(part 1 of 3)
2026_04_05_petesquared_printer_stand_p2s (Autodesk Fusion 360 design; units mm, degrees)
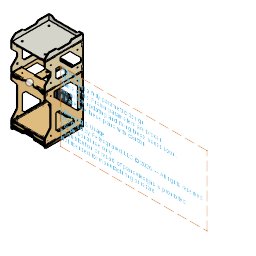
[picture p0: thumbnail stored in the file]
parameter "material_thickness" = 12.192
parameter "printer_width_padding" = 482.6 (= "ceil(printer_width_adjusted + 1 in)")
parameter "printer_length_padding" = 609.6 (= "ceil(printer_length_adjusted + 4 in)")
parameter "printer_height_padding" = 736.6 (= "ceil(printer_height_adjusted + global_shelf_height + printer_height_pad)")
parameter "global_shelf_height" = 71.12
parameter "shelf_padding_sides" = 28.702 (= "material_thickness + 0.65 in")
parameter "ams_height" = 223.012
parameter "global_shelf_width" = 428.498 (= "printer_width_adjusted - shelf_padding_sides")
parameter "global_shelf_length" = 457.2
parameter "filament_height" = 228.6
parameter "base_height" = 38.1
parameter "poop_height" = 101.6
parameter "hole_bolt" = 10.414 comment "The furniture bolts for bolting stand and shelves togther"
parameter "dado_bolthead_diameter" = 16.256 comment "Head size of furniture bolts for bolting stand and shelves togther"
parameter "dado_bolthead_depth" = 3.048 comment "The inset dado to fit the furniture bolt heads flush with plywood surface"
parameter "bolt_side_offset" = 76.2
parameter "handle_inset_depth" = 19.05
parameter "handle_angle_side" = 15
parameter "handle_width" = 152.4
parameter "global_cutout_padding" = 44.45
parameter "global_cutout_corner_round" = 12.7
parameter "shelf_runner_inset" = 15.748 comment "If you are using different drawer runners this will need to be adjusted."
parameter "dado_material_thickness" = 12.446 (= "material_thickness + 0.01 in")
parameter "dado_material_depth" = 4.572
parameter "hole_screw" = 3.2004
parameter "hole_screwhead" = 7.112
parameter "dado_screwhead_depth" = 3.302
parameter "switch_diameter" = 25.4
parameter "printer_width" = 388.9375 (= "15 5/16")
parameter "printer_width_adjusted" = 457.2 (= "ceil(( min(60 in; max(12 in; printer_width)) ) + printer_width_pad)")
parameter "printer_width_pad" = 50.8
parameter "printer_length" = 388.9375 (= "15 5/16")
parameter "printer_length_adjusted" = 508 (= "ceil(( min(60 in; max(12 in; printer_length)) ) + printer_length_pad)")
parameter "printer_length_pad" = 101.6
parameter "printer_height" = 466.725 (= "18 3/8")
parameter "printer_height_pad" = 50.8
parameter "hole_screw_inset" = 38.1
parameter "hole_screws_width_distance" = 381 (= "( printer_width_adjusted - ( hole_screw_inset * 2 ) )")
parameter "hole_screws_length_distance" = 431.8 (= "( printer_length_adjusted - ( hole_screw_inset * 2 ) )")
parameter "hole_screws_printer_height_distance" = 533.4 (= "( printer_height_adjusted - ( hole_screw_inset * 2 ) )")
parameter "hole_switch_button" = 19.431
parameter "milling_pins_twosided" = 9.525
parameter "storage_height" = 25.4
parameter "slot_screw_width" = 38.1
parameter "dado_screwhead_carpentry" = 10.16
parameter "hole_screws_ams_height_distance" = 279.4 (= "( ams_height_adjusted - ( hole_screw_inset * 2 ) )")
parameter "ams_height_pad" = 50.8 comment "adjusts the padding space above the ams"
parameter "filament_height_pad" = 0 comment "adjusts the padding space above the filament"
parameter "hole_screws_filament_height_distance" = 228.6 (= "( filament_height_adjusted - ( hole_screw_inset * 2 ) )")
parameter "storage_height_pad" = 76.2
parameter "hole_screws_storage_height_distance" = 101.6 (= "( storage_height_adjusted - ( hole_screw_inset * 2 ) )")
parameter "poop_height_pad" = 25.4
parameter "hole_screws_poop_height_distance" = 177.8 (= "( poop_height_adjusted - ( hole_screw_inset * 2 ) )")
parameter "brace_length" = 139.7
parameter "hole_screw_brace_offset" = 25.4
parameter "wall_thickness_3d_printed" = 4.572
parameter "runner_thickness" = 13.1572
parameter "hole_screw_3dprint" = 3.81
parameter "hole_threaded_inserts" = 12.192
parameter "d545" = 25.4
parameter "d546" = 25.4 (= "d545")
parameter "d2170" = 12.7
parameter "d2974" = 19.05
sketch "printer_width_length" plane through (0, 0, 0) normal (0, 0, 1) x axis (1, 0, 0)
  line L1 (194.4688, 388.9375) -> (-194.4688, 388.9375)
  line L2 (194.4688, 0) -> (194.4688, 388.9375)
  line L3 (-194.4688, 0) -> (194.4688, 0)
  line L4 (-194.4688, 388.9375) -> (-194.4688, 0)
  line L5 (0, 0) -> (0, 388.9375)
  line L6 (194.4688, 194.4688) -> (-194.4688, 194.4688)
  point P6 (0, 0)
  point P1 (0, 0)
  point P7 (0, 388.9375)
  point P8 (0, 0)
  point P9 (-194.4688, 194.4688)
  point P10 (194.4688, 194.4688)
  point P11 (0, 194.4688)
  point P3 (194.4688, 388.9375)
  point P4 (194.4688, 0)
  point P5 (-194.4688, 0)
  horizontal L1
  vertical L2
  horizontal L3
  vertical L4
  midpoint L3 P6
  coincident P1 P6
  midpoint L1 P7
  coincident P6 P8
  midpoint L4 P9
  midpoint L2 P10
  midpoint L5 P11
  dimension "d2" distance P3 P4 = 388.9375 (= "printer_length")
  dimension "d24" distance P4 P5 = 388.9375 (= "printer_width")
work_plane "WorkPlane7" AlongDistance 0
work_plane "WorkPlane6" AlongDistance 466.725 (= "printer_height")
work_plane "WorkPlane3" RotateAngle 90
work_plane "WorkPlane4" RotateAngle 90
work_plane "WorkPlane5" RotateAngle 90
sketch "printer_length_height" plane through (194.4687, 0, 0) normal (-1, 0, 0) x axis (0, -1, 0)
  line L1 (0, 0) -> (-388.9375, 0)
  line L2 (0, 466.725) -> (0, 0)
  line L3 (-388.9375, 466.725) -> (0, 466.725)
  line L4 (-388.9375, 0) -> (-388.9375, 466.725)
  line L5 (-194.4687, 466.725) -> (-194.4688, 0)
  line L6 (-388.9375, 233.3625) -> (0, 233.3625)
  point P3 (0, 0)
  point P4 (0, 0)
  point P2 (-388.9375, 0)
  point P7 (-388.9375, 0)
  point P8 (-194.4688, 0)
  point P9 (-194.4687, 466.725)
  point P10 (0, 233.3625)
  point P11 (-388.9375, 233.3625)
  point P12 (-194.4687, 233.3625)
  point P5 (0, 466.725)
  coincident P3 P4
  perpendicular L1 L2
  perpendicular L2 L3
  coincident P2 P7
  perpendicular L1 L4
  midpoint L1 P8
  midpoint L3 P9
  midpoint L2 P10
  midpoint L4 P11
  midpoint L5 P12
  dimension "d23" distance P4 P5 = 466.725 (= "printer_height")
sketch "printer_height_length" plane through (0, 388.9375, 0) normal (0, -1, 0) x axis (-1, 0, 0)
  line L1 (-194.4688, 0) -> (-194.4688, -466.725)
  line L2 (-194.4688, 0) -> (194.4688, 0)
  line L3 (194.4688, -466.725) -> (-194.4688, -466.725)
  line L4 (194.4688, 0) -> (194.4688, -466.725)
  line L5 (0, 0) -> (0, -466.725)
  line L6 (194.4688, -233.3625) -> (-194.4688, -233.3625)
  point P2 (-194.4688, -466.725)
  point P6 (-194.4688, -466.725)
  point P4 (194.4688, 0)
  point P8 (194.4688, 0)
  point P9 (0, -466.725)
  point P1 (0, 0)
  point P10 (0, 0)
  point P11 (-194.4688, -233.3625)
  point P12 (194.4688, -233.3625)
  point P13 (0, -233.3625)
  coincident P2 P6
  perpendicular L1 L3
  coincident P4 P8
  perpendicular L2 L4
  midpoint L3 P9
  coincident P1 P10
  midpoint L1 P11
  midpoint L4 P12
  midpoint L6 P13
extrude "Extrude1" new body sketch "printer_width_length" profile of L1 L2 L3 L4 along normal blind 466.725 (= "printer_height") bodies "printer_size"
fillet "Fillet1" radius 40.64
work_plane "WorkPlane5"
work_plane "WorkPlane1" AlongDistance 538.48 (= "printer_height_adjusted - global_shelf_height")
work_plane "WorkPlane2" AlongDistance 508 (= "printer_length_adjusted")
work_plane "WorkPlane7" RotateAngle 0
work_plane "WorkPlane6" RotateAngle 90
work_plane "WorkPlane8" AlongDistance 228.6 (= "printer_width_adjusted / 2")
work_plane "WorkPlane4" AlongDistance 304.8 (= "printer_height_adjusted / 2")
work_plane "WorkPlane9" AlongDistance 0
sketch "printer_bottom" plane through (0, 0, -71.12) normal (0, 0, 1) x axis (1, 0, 0)
  line L1 (228.6, 508) -> (-228.6, 508)
  line L2 (228.6, 0) -> (228.6, 508)
  line L3 (-228.6, 0) -> (228.6, 0)
  line L4 (-228.6, 508) -> (-228.6, 0)
  line L5 (152.4, 76.2) -> (152.4, 431.8)
  line L6 (-152.4, 76.2) -> (152.4, 76.2)
  line L7 (-152.4, 431.8) -> (-152.4, 76.2)
  line L8 (152.4, 431.8) -> (-152.4, 431.8)
  line L9 (48.9938, 19.05) -> (-48.9938, 19.05)
  line L10 (216.408, 12.192) -> (220.98, 12.192)
  line L11 (0, 0) -> (0, 508)
  line L12 (-216.408, 12.192) -> (-220.98, 12.192)
  line L13 (-220.98, 508) -> (-220.98, 12.192)
  line L14 (220.98, 12.192) -> (220.98, 508)
  line L15 (228.6, 254) -> (-228.6, 254)
  line L16 (0, 254) -> (-228.6, 508)
  line L17 (228.6, 508) -> (0, 254)
  line L18 (-228.6, 0) -> (0, 254)
  line L19 (228.6, 0) -> (0, 254)
  line L20 (-81.28, 500.38) -> (-220.98, 500.38)
  line L21 (-220.98, 500.38) -> (-220.98, 360.68)
  line L22 (-204.216, 360.68) -> (-220.98, 360.68)
  line L23 (-81.28, 483.616) -> (-81.28, 500.38)
  line L24 (220.98, 139.7) -> (-220.98, 139.7)
  line L25 (-103.0086, 418.3296) -> (-81.28, 483.616)
  line L26 (-204.216, 360.68) -> (-138.9296, 382.4086)
  line L27 (216.408, 12.192) -> (165.608, 0)
  line L28 (-76.2, 0) -> (-48.9938, 19.05)
  line L29 (76.2, 0) -> (48.9938, 19.05)
  line L30 (-216.408, 12.192) -> (-165.608, 0)
  line L31 (220.98, 12.192) -> (220.98, 139.7)
  line L32 (-220.98, 12.192) -> (-220.98, 139.7)
  line L33 (-120.9691, 400.3691) -> (-220.98, 500.38)
  line L34 (-103.0086, 418.3296) -> (-138.9296, 382.4086)
  line L35 (103.0086, 418.3296) -> (138.9296, 382.4086)
  line L36 (204.216, 360.68) -> (138.9296, 382.4086)
  line L37 (204.216, 360.68) -> (220.98, 360.68)
  line L38 (220.98, 500.38) -> (220.98, 360.68)
  line L39 (81.28, 500.38) -> (220.98, 500.38)
  line L40 (81.28, 483.616) -> (81.28, 500.38)
  line L41 (103.0086, 418.3296) -> (81.28, 483.616)
  circle C1 centre (-152.4, 431.8) radius 5.207
  circle C2 centre (-152.4, 431.8) radius 8.128
  circle C3 centre (152.4, 431.8) radius 8.128
  circle C4 centre (152.4, 431.8) radius 5.207
  circle C5 centre (-152.4, 76.2) radius 5.207
  circle C6 centre (-152.4, 76.2) radius 8.128
  circle C7 centre (152.4, 76.2) radius 5.207
  circle C8 centre (152.4, 76.2) radius 8.128
  point P6 (0, 0)
  point P7 (0, 0)
  point P11 (-152.4, 431.8)
  point P12 (-152.4, 431.8)
  point P8 (152.4, 431.8)
  point P14 (152.4, 431.8)
  point P15 (152.4, 431.8)
  point P10 (-152.4, 76.2)
  point P16 (-152.4, 76.2)
  point P9 (152.4, 76.2)
  point P18 (152.4, 76.2)
  point P20 (-76.2, 0)
  point P23 (76.2, 0)
  point P24 (0, 19.05)
  point P26 (165.608, 0)
  point P27 (0, 508)
  point P28 (0, 0)
  point P25 (216.408, 12.192)
  point P30 (-216.408, 12.192)
  point P31 (-220.98, 12.192)
  point P35 (-228.6, 254)
  point P36 (228.6, 254)
  point P37 (0, 254)
  point P48 (-216.408, 12.192)
  point P47 (-165.608, 0)
  point P39 (-220.98, 360.68)
  point P49 (220.98, 139.7)
  point P29 (-220.98, 12.192)
  point P43 (-220.98, 139.7)
  point P46 (-120.9691, 400.3691)
  point P50 (-120.9691, 400.3691)
  point P32 (-220.98, 508)
  point P33 (220.98, 508)
  point P38 (-220.98, 500.38)
  point P55 (220.98, 500.38)
  point P54 (220.98, 360.68)
  point P40 (-204.216, 360.68)
  point P53 (204.216, 360.68)
  point P41 (-81.28, 500.38)
  point P56 (81.28, 500.38)
  point P42 (-81.28, 483.616)
  point P57 (81.28, 483.616)
  point P44 (-103.0086, 418.3296)
  point P52 (103.0086, 418.3296)
  point P45 (-138.9296, 382.4086)
  point P51 (138.9296, 382.4086)
  point P4 (228.6, 0)
  point P5 (-228.6, 0)
  point P2 (-228.6, 508)
  point P34 (220.98, 12.192)
  point P13 (-152.4, 431.8)
  horizontal L1
  vertical L2
  horizontal L3
  vertical L4
  midpoint L3 P6
  coincident P6 P7
  coincident P11 P12
  concentric C1 C2
  coincident P8 P14
  coincident P8 P15
  coincident P10 P16
  concentric C5 C6
  coincident P9 P18
  concentric C7 C8
  coincident L3 P20
  parallel L6 L9
  coincident L3 P23
  midpoint L9 P24
  vertical P6 P24
  perpendicular L2 L10
  coincident L3 P26
  midpoint L1 P27
  coincident P7 P28
  symmetric P25 L11 P30
  coincident L12 P31
  midpoint L4 P35
  midpoint L2 P36
  midpoint L15 P37
  vertical L21
  horizontal L20
  perpendicular L21 L22
  perpendicular L20 L23
  equal L20 L21
  equal L22 L23
  perpendicular L2 L24
  equal L25 L26
  equal L28 L29
  symmetric P25 L11 P48
  symmetric P26 L11 P47
  coincident L13 P39
  coincident L14 P49
  horizontal L12
  coincident P29 P31
  coincident L13 P43
  coincident P46 P50
  midpoint P46 L34
  coincident L1 P32
  coincident L1 P33
  symmetric L11 P38 P55
  symmetric L11 P39 P54
  symmetric L11 P40 P53
  symmetric L11 P41 P56
  symmetric L11 P42 P57
  symmetric L11 P44 P52
  symmetric L11 P45 P51
  dimension "d50" distance P4 P5 = 457.2 (= "printer_width_adjusted")
  dimension "d51" distance P2 P5 = 508 (= "printer_length_adjusted")
  dimension "d193" = 76.2 (= "bolt_side_offset")
  dimension "d194" diameter C1 = 10.414 (= "hole_bolt")
  dimension "d195" diameter C2 = 16.256 (= "dado_bolthead_diameter")
  dimension "d196" diameter C3 = 16.256 (= "dado_bolthead_diameter")
  dimension "d197" diameter C4 = 10.414 (= "hole_bolt")
  dimension "d198" diameter C5 = 10.414 (= "hole_bolt")
  dimension "d199" diameter C6 = 16.256 (= "dado_bolthead_diameter")
  dimension "d200" diameter C7 = 10.414 (= "hole_bolt")
  dimension "d201" diameter C8 = 16.256 (= "dado_bolthead_diameter")
  dimension "d218" distance P6 P24 = 19.05 (= "handle_inset_depth")
  dimension "d223" distance P20 P23 = 152.4 (= "handle_width")
  dimension "d331" distance P25 P26 = 50.8
  dimension "d493" = 7.62 (= "material_thickness - dado_material_depth")
  dimension "d2502" distance P39 P40 = 16.764 (= "material_thickness + dado_material_depth")
  dimension "d2539" angle L9 L29 = 145
  dimension "d2589" distance P4 P49 = 139.7 (= "brace_length")
  dimension "d2590" distance P4 P34 = 12.192 (= "material_thickness")
  dimension "d2591" distance P4 P25 = 12.192 (= "material_thickness")
  dimension "d2937" angle L20 L33 = 45
  dimension "d2938" distance P44 P45 = 50.8
  dimension "d2939" distance P2 P38 = 7.62 (= "material_thickness - dado_material_depth")
  dimension "d2940" distance P13 P46 = 44.45
  dimension "d2950" distance P38 P41 = 139.7 (= "brace_length")
sketch "printer_side_right" plane through (228.6, 0, 0) normal (1, 0, 0) x axis (0, 1, 0)
  line L1 (508, -71.12) -> (0, -71.12)
  line L2 (508, 538.48) -> (508, -71.12)
  line L3 (0, 538.48) -> (508, 538.48)
  line L4 (76.2, 5.08) -> (76.2, 462.28)
  line L5 (431.8, 5.08) -> (76.2, 5.08)
  line L6 (431.8, 462.28) -> (431.8, 5.08)
  line L7 (76.2, 462.28) -> (431.8, 462.28)
  line L8 (508, 233.68) -> (0, 233.68)
  line L9 (495.808, 526.288) -> (495.808, -58.928)
  line L10 (12.192, 538.48) -> (12.192, 526.288)
  line L11 (12.192, -71.12) -> (12.192, -58.928)
  line L12 (30.734, 488.188) -> (18.542, 488.188)
  line L13 (30.734, 526.288) -> (30.734, 488.188)
  line L14 (18.542, 488.188) -> (18.542, 526.288)
  line L15 (483.616, 467.36) -> (483.616, 526.288)
  line L16 (495.808, 467.36) -> (483.616, 467.36)
  line L17 (254, 233.68) -> (0, 538.48)
  line L18 (254, 233.68) -> (508, 538.48)
  line L19 (0, -71.12) -> (254, 233.68)
  line L20 (508, -71.12) -> (254, 233.68)
  line L21 (76.2, 370.84) -> (0, 462.28)
  line L22 (0, 5.08) -> (76.2, 96.52)
  line L23 (76.2, 96.52) -> (76.2, 370.84)
  line L24 (483.616, 118.7418) -> (483.616, 347.6022)
  line L25 (142.875, 37.4682) -> (142.875, 237.4932)
  line L26 (180.3432, 0) -> (387.35, 0)
  line L27 (120.65, 494.03) -> (337.1882, 494.03)
  line L28 (387.35, 37.4682) -> (387.35, 0)
  line L29 (387.35, 37.4682) -> (187.325, 237.4932)
  line L30 (483.616, 118.7418) -> (431.8, 118.7418)
  line L31 (180.3432, 0) -> (142.875, 37.4682)
  line L32 (187.325, 237.4932) -> (142.875, 237.4932)
  line L33 (483.616, 347.6022) -> (337.1882, 494.03)
  line L34 (120.65, 429.8918) -> (120.65, 494.03)
  line L35 (0, 462.28) -> (0, 538.48)
  line L36 (0, -71.12) -> (0, 5.08)
  line L37 (139.7, -58.928) -> (139.7, -71.12)
  line L38 (360.68, -58.928) -> (360.68, -71.12)
  line L39 (139.7, 526.288) -> (139.7, 538.48)
  line L40 (360.68, 526.288) -> (360.68, 538.48)
  line L41 (12.192, 526.288) -> (18.542, 526.288)
  line L42 (431.8, 118.7418) -> (120.65, 429.8918)
  line L43 (139.7, -58.928) -> (12.192, -58.928)
  line L44 (360.68, 526.288) -> (495.808, 526.288)
  line L45 (30.734, 526.288) -> (139.7, 526.288)
  line L46 (495.808, -58.928) -> (360.68, -58.928)
  line L47 (495.808, 538.48) -> (495.808, 526.288)
  line L48 (495.808, -71.12) -> (495.808, -58.928)
  line L49 (483.616, 0) -> (483.616, -58.928)
  line L50 (495.808, 0) -> (483.616, 0)
  circle C1 centre (76.2, 5.08) radius 5.207
  circle C2 centre (76.2, 5.08) radius 8.128
  circle C3 centre (431.8, 5.08) radius 5.207
  circle C4 centre (431.8, 5.08) radius 8.128
  circle C5 centre (76.2, 462.28) radius 5.207
  circle C6 centre (76.2, 462.28) radius 8.128
  circle C7 centre (431.8, 462.28) radius 5.207
  circle C8 centre (431.8, 462.28) radius 8.128
  circle C9 centre (489.712, 509.3547) radius 1.6002
  circle C10 centre (489.712, 484.2933) radius 1.6002
  circle C11 centre (37.592, 532.384) radius 1.6002
  circle C12 centre (114.3, 532.384) radius 1.6002
  circle C13 centre (386.08, 532.384) radius 1.6002
  circle C14 centre (470.408, 532.384) radius 1.6002
  circle C15 centre (489.712, -41.9947) radius 1.6002
  circle C16 centre (489.712, -16.9333) radius 1.6002
  circle C17 centre (37.592, -65.024) radius 1.6002
  circle C18 centre (114.3, -65.024) radius 1.6002
  circle C19 centre (386.08, -65.024) radius 1.6002
  circle C20 centre (470.408, -65.024) radius 1.6002
  circle C21 centre (501.904, 233.68) radius 1.6002
  circle C22 centre (501.904, -42.418) radius 1.6002
  circle C23 centre (501.904, 95.631) radius 1.6002
  circle C24 centre (501.904, 371.729) radius 1.6002
  circle C25 centre (501.904, 509.778) radius 1.6002
  point P2 (0, -71.12)
  point P6 (0, -71.12)
  point P7 (76.2, 5.08)
  point P16 (76.2, 5.08)
  point P9 (431.8, 5.08)
  point P17 (431.8, 5.08)
  point P11 (76.2, 462.28)
  point P15 (76.2, 462.28)
  point P14 (431.8, 462.28)
  point P18 (431.8, 462.28)
  point P20 (508, 233.68)
  point P25 (12.192, 538.48)
  point P26 (12.192, -71.12)
  point P29 (24.638, 488.188)
  point P21 (12.192, 526.288)
  point P30 (12.192, 526.288)
  point P32 (495.808, 467.36)
  point P33 (489.712, 467.36)
  point P35 (489.712, 484.2933)
  point P36 (254, 233.68)
  point P3 (508, -71.12)
  point P37 (508, -71.12)
  point P43 (387.35, 37.4682)
  point P46 (142.875, 37.4682)
  point P31 (483.616, 467.36)
  point P51 (483.616, 347.6022)
  point P19 (0, 233.68)
  point P54 (139.7, -71.12)
  point P60 (139.7, -71.12)
  point P61 (139.7, 538.48)
  point P63 (360.68, 538.48)
  point P68 (12.192, 532.384)
  point P67 (37.592, 532.384)
  point P69 (114.3, 532.384)
  point P65 (18.542, 526.288)
  point P66 (30.734, 526.288)
  point P70 (360.68, 532.384)
  point P71 (386.08, 532.384)
  point P72 (470.408, 532.384)
  point P12 (76.2, 462.28)
  point P38 (0, 462.28)
  point P8 (76.2, 5.08)
  point P39 (0, 5.08)
  point P55 (139.7, -58.928)
  point P57 (360.68, -58.928)
  point P73 (483.616, 526.288)
  point P74 (495.808, 538.48)
  point P75 (495.808, -71.12)
  point P34 (489.712, 509.3547)
  point P77 (483.616, 0)
  point P78 (495.808, 0)
  point P76 (483.616, -58.928)
  point P81 (139.7, -65.024)
  point P83 (114.3, -65.024)
  point P82 (37.592, -65.024)
  point P84 (386.08, -65.024)
  point P85 (470.408, -65.024)
  point P86 (501.904, 233.68)
  point P56 (360.68, -71.12)
  point P91 (360.68, -71.12)
  point P44 (431.8, 118.7418)
  point P27 (18.542, 488.188)
  point P28 (30.734, 488.188)
  point P42 (387.35, 0)
  point P48 (142.875, 237.4932)
  point P49 (187.325, 237.4932)
  point P5 (0, 538.48)
  point P52 (120.65, 494.03)
  point P59 (0, -71.12)
  point P22 (12.192, -58.928)
  point P4 (508, 538.48)
  point P24 (495.808, 526.288)
  point P23 (495.808, -58.928)
  point P10 (431.8, 5.08)
  point P13 (431.8, 462.28)
  vertical L2
  horizontal L3
  vertical L35
  coincident P2 P6
  concentric C1 C2
  concentric C3 C4
  concentric C5 C6
  concentric C7 C8
  coincident P7 P16
  coincident P9 P17
  coincident P11 P15
  coincident P14 P18
  midpoint L2 P20
  coincident L3 P25
  coincident L1 P26
  midpoint L12 P29
  vertical L13
  coincident P21 P30
  vertical L14
  coincident L9 P32
  perpendicular L9 L16
  midpoint L16 P33
  vertical P33 P35
  midpoint L8 P36
  parallel L17 L21
  parallel L19 L22
  coincident P3 P37
  parallel L4 L23
  vertical L24
  parallel L25 L35
  horizontal L26
  horizontal L27
  perpendicular L26 L28
  perpendicular L24 L30
  horizontal P43 P46
  perpendicular L25 L32
  perpendicular L27 L34
  vertical P31 P51
  collinear L35 L36
  vertical P2 P19
  collinear L4 L23
  horizontal L5
  horizontal L7
  vertical L6
  horizontal L44
  coincident P54 P60
  coincident L3 P61
  coincident L3 P63
  horizontal L43
  vertical L37
  vertical L11
  vertical L38
  vertical L10
  horizontal L41
  horizontal L12
  midpoint L10 P68
  horizontal P67 P68
  horizontal P68 P69
  vertical L39
  vertical L40
  horizontal P65 P66
  vertical L9
  midpoint L40 P70
  horizontal P70 P71
  horizontal P70 P72
  horizontal L8
  collinear L44 L45
  horizontal P12 P38
  horizontal P8 P39
  perpendicular L2 L46
  horizontal P55 P57
  coincident L44 P73
  perpendicular L3 L47
  coincident L3 P74
  coincident L1 P75
  perpendicular L1 L48
  vertical P33 P34
  vertical L15
  symmetric L8 P31 P77
  symmetric L8 P32 P78
  symmetric L8 C9 C15
  symmetric L8 C10 C16
  symmetric L8 P73 P76
  midpoint L37 P81
  horizontal P81 P83
  horizontal P81 P82
  horizontal P81 P84
  horizontal P81 P85
  coincident L8 P86
  coincident P56 P91
  coincident L6 P44
  dimension "d49" distance P2 P3 = 508 (= "printer_length_adjusted")
  dimension "d176" diameter C1 = 10.414 (= "hole_bolt")
  dimension "d177" diameter C2 = 16.256 (= "dado_bolthead_diameter")
  dimension "d180" diameter C3 = 10.414 (= "hole_bolt")
  dimension "d181" diameter C4 = 16.256 (= "dado_bolthead_diameter")
  dimension "d184" diameter C5 = 10.414 (= "hole_bolt")
  dimension "d185" diameter C6 = 16.256 (= "dado_bolthead_diameter")
  dimension "d188" diameter C7 = 10.414 (= "hole_bolt")
  dimension "d189" diameter C8 = 16.256 (= "dado_bolthead_diameter")
  dimension "d641" distance P27 P28 = 12.192 (= "material_thickness")
  dimension "d648" diameter C9 = 3.2004 (= "hole_screw")
  dimension "d650" diameter C10 = 3.2004 (= "hole_screw")
  dimension "d2190" distance L1 L3 = 609.6 (= "printer_height_adjusted")
  dimension "d2513" distance L4 L25 = 66.675 (= "global_cutout_padding * 1.5")
  dimension "d2517" distance P3 P42 = 71.12 (= "global_shelf_height")
  dimension "d2520" angle L26 L31 = 135
  dimension "d2521" distance P48 P49 = 44.45 (= "global_cutout_padding")
  dimension "d2522" angle L24 L33 = 135
  dimension "d2524" distance P5 P52 = 44.45 (= "global_cutout_padding")
  dimension "d2533" distance L6 P20 = 76.2 (= "bolt_side_offset")
  dimension "d2543" distance P8 P59 = 76.2 (= "bolt_side_offset")
  dimension "d2646" distance P5 P61 = 139.7 (= "brace_length")
  dimension "d2694" distance P22 P26 = 12.192 (= "material_thickness")
  dimension "d2695" distance P21 P25 = 12.192 (= "material_thickness")
  dimension "d2696" distance P27 P65 = 38.1
  dimension "d2697" distance P21 P65 = 6.35
  dimension "d2698" distance P5 P25 = 12.192 (= "material_thickness")
  dimension "d2699" diameter C11 = 3.2004 (= "hole_screw")
  dimension "d2700" distance P25 P67 = 25.4 (= "hole_screw_brace_offset")
  dimension "d2701" diameter C12 = 3.2004 (= "hole_screw")
  dimension "d2702" distance P61 P69 = 25.4 (= "hole_screw_brace_offset")
  dimension "d2704" diameter C13 = 3.2004 (= "hole_screw")
  dimension "d2705" diameter C14 = 3.2004 (= "hole_screw")
  dimension "d2706" distance P70 P71 = 25.4 (= "hole_screw_brace_offset")
  dimension "d2765" angle L29 L32 = 135
  dimension "d2766" distance P36 L29 = 44.45 (= "global_cutout_padding")
  dimension "d2767" angle L30 L42 = 135
  dimension "d2901" distance P2 P26 = 12.192 (= "material_thickness")
  dimension "d2903" distance L3 L7 = 76.2 (= "bolt_side_offset")
  dimension "d2904" distance P19 L23 = 76.2 (= "bolt_side_offset")
  dimension "d2905" distance P4 P74 = 12.192 (= "material_thickness")
  dimension "d2906" distance P24 P73 = 12.192 (= "material_thickness")
  dimension "d2908" distance P33 P35 = 16.9333 (= "hole_screw_brace_offset / 1.5")
  dimension "d2909" distance P24 P34 = 16.9333 (= "hole_screw_brace_offset / 1.5")
  dimension "d2916" diameter C17 = 3.2004 (= "hole_screw")
  dimension "d2917" diameter C18 = 3.2004 (= "hole_screw")
  dimension "d2918" distance P81 P83 = 25.4 (= "hole_screw_brace_offset")
  dimension "d2919" distance P22 P82 = 25.4 (= "hole_screw_brace_offset")
  dimension "d2920" diameter C19 = 3.2004 (= "hole_screw")
  dimension "d2921" distance P57 P84 = 25.4 (= "hole_screw_brace_offset")
  dimension "d2922" diameter C20 = 3.2004 (= "hole_screw")
  dimension "d2923" distance P23 P85 = 25.4 (= "hole_screw_brace_offset")
  dimension "d2924" diameter C21 = 3.2004 (= "hole_screw")
  dimension "d2925" distance P20 P86 = 6.096 (= "material_thickness / 2")
  dimension "d2941" distance P72 P74 = 25.4 (= "hole_screw_brace_offset")
  dimension "d2942" distance P10 P42 = 44.45 (= "global_cutout_padding")
  dimension "d2943" distance P13 L33 = 44.45 (= "global_cutout_padding")
  dimension "d2945" distance P36 L42 = 44.45 (= "global_cutout_padding")
  dimension "d2949" distance P63 P74 = 135.128 (= "brace_length - dado_material_depth")
  dimension "d3023" distance P4 P31 = 71.12 (= "global_shelf_height")
  dimension "d3555" distance P12 L34 = 44.45 (= "global_cutout_padding")
  dimension "d2928" R-Pattern1-uDistance = 0
  dimension "d2929" R-Pattern1-vDistance = 276.098
sketch "printer_back" plane through (0, 508, 0) normal (0, 1, 0) x axis (1, 0, 0)
  line L1 (228.6, 71.12) -> (-228.6, 71.12)
  line L2 (228.6, -538.48) -> (228.6, 71.12)
  line L3 (-228.6, -538.48) -> (228.6, -538.48)
  line L4 (-228.6, 71.12) -> (-228.6, -538.48)
  line L5 (0, 71.12) -> (0, -538.48)
  line L6 (-228.6, -233.68) -> (228.6, -233.68)
  line L7 (220.98, -538.48) -> (220.98, 71.12)
  line L8 (-220.98, -467.36) -> (220.98, -467.36)
  line L9 (-220.98, 0) -> (220.98, 0)
  line L10 (161.925, 0) -> (161.925, -467.36)
  line L11 (81.28, 71.12) -> (81.28, 58.928)
  line L12 (81.28, -526.034) -> (81.28, -538.48)
  line L13 (-220.98, -526.034) -> (220.98, -526.034)
  line L14 (-220.98, 58.928) -> (220.98, 58.928)
  line L15 (161.925, -526.034) -> (161.925, -467.36)
  line L16 (161.925, 58.928) -> (161.925, 0)
  line L17 (161.925, -538.48) -> (161.925, -526.034)
  line L18 (161.925, 71.12) -> (161.925, 58.928)
  line L19 (-220.98, 71.12) -> (-220.98, -538.48)
  line L20 (-161.925, -538.48) -> (-161.925, -526.034)
  line L21 (-161.925, -526.034) -> (-161.925, -467.36)
  line L22 (-161.925, 0) -> (-161.925, -467.36)
  line L23 (-161.925, 58.928) -> (-161.925, 0)
  line L24 (-161.925, 71.12) -> (-161.925, 58.928)
  line L25 (-81.28, -526.034) -> (-81.28, -538.48)
  line L26 (-81.28, 71.12) -> (-81.28, 58.928)
  line L27 (220.98, -496.697) -> (161.925, -496.697)
  line L28 (-220.98, -496.697) -> (-161.925, -496.697)
  line L29 (-220.98, 29.337) -> (-161.925, 29.337)
  line L30 (220.98, 29.337) -> (161.925, 29.337)
  line L31 (19.05, -508.3302) -> (-19.05, -508.3302)
  line L32 (-19.05, -505.1298) -> (19.05, -505.1298)
  line L33 (19.05, -506.73) -> (-19.05, -506.73)
  line L34 (-19.05, -500.0498) -> (19.05, -500.0498)
  line L35 (19.05, -513.4102) -> (-19.05, -513.4102)
  line L36 (-146.05, -513.4102) -> (-184.15, -513.4102)
  line L37 (-184.15, -500.0498) -> (-146.05, -500.0498)
  line L38 (-146.05, -508.3302) -> (-184.15, -508.3302)
  line L39 (-184.15, -505.1298) -> (-146.05, -505.1298)
  line L40 (184.15, -513.4102) -> (146.05, -513.4102)
  line L41 (146.05, -500.0498) -> (184.15, -500.0498)
  line L42 (184.15, -508.3302) -> (146.05, -508.3302)
  line L43 (146.05, -505.1298) -> (184.15, -505.1298)
  line L44 (191.4525, -467.36) -> (191.4525, -496.697)
  circle C1 centre (195.58, -532.257) radius 1.6002
  arc A1 centre (19.05, -506.73) radius 1.6002 clockwise from (19.05, -505.1298) to (19.05, -508.3302)
  arc A2 centre (-19.05, -506.73) radius 1.6002 clockwise from (-19.05, -508.3302) to (-19.05, -505.1298)
  arc A3 centre (-19.05, -506.73) radius 6.6802 clockwise from (-19.05, -513.4102) to (-19.05, -500.0498)
  arc A4 centre (19.05, -506.73) radius 6.6802 clockwise from (19.05, -500.0498) to (19.05, -513.4102)
  arc A5 centre (-146.05, -506.73) radius 6.6802 clockwise from (-146.05, -500.0498) to (-146.05, -513.4102)
  arc A6 centre (-184.15, -506.73) radius 6.6802 clockwise from (-184.15, -513.4102) to (-184.15, -500.0498)
  arc A7 centre (-146.05, -506.73) radius 1.6002 clockwise from (-146.05, -505.1298) to (-146.05, -508.3302)
  arc A8 centre (-184.15, -506.73) radius 1.6002 clockwise from (-184.15, -508.3302) to (-184.15, -505.1298)
  arc A9 centre (184.15, -506.73) radius 6.6802 clockwise from (184.15, -500.0498) to (184.15, -513.4102)
  arc A10 centre (146.05, -506.73) radius 6.6802 clockwise from (146.05, -513.4102) to (146.05, -500.0498)
  arc A11 centre (184.15, -506.73) radius 1.6002 clockwise from (184.15, -505.1298) to (184.15, -508.3302)
  arc A12 centre (146.05, -506.73) radius 1.6002 clockwise from (146.05, -508.3302) to (146.05, -505.1298)
  circle C2 centre (207.9625, -482.0285) radius 1.6002
  circle C3 centre (106.68, -532.257) radius 1.6002
  circle C4 centre (-195.58, -532.257) radius 1.6002
  circle C5 centre (-106.68, -532.257) radius 1.6002
  circle C6 centre (195.58, 64.897) radius 1.6002
  circle C7 centre (106.68, 64.897) radius 1.6002
  circle C8 centre (-106.68, 64.897) radius 1.6002
  circle C9 centre (-195.58, 64.897) radius 1.6002
  circle C10 centre (174.9425, -482.0285) radius 1.6002
  circle C11 centre (-174.9425, -482.0285) radius 1.6002
  circle C12 centre (-207.9625, -482.0285) radius 1.6002
  circle C13 centre (207.9625, 14.6685) radius 1.6002
  circle C14 centre (174.9425, 14.6685) radius 1.6002
  circle C15 centre (-174.9425, 14.6685) radius 1.6002
  circle C16 centre (-207.9625, 14.6685) radius 1.6002
  point P5 (228.6, -538.48)
  point P6 (228.6, -538.48)
  point P2 (-228.6, 71.12)
  point P8 (-228.6, 71.12)
  point P9 (0, -538.48)
  point P10 (0, 71.12)
  point P11 (228.6, -233.68)
  point P12 (-228.6, -233.68)
  point P13 (0, -550.799)
  point P16 (220.98, -467.36)
  point P19 (220.98, 0)
  point P22 (161.925, -467.36)
  point P23 (161.925, 0)
  point P27 (81.28, 71.12)
  point P29 (81.28, -538.48)
  point P30 (81.28, -526.034)
  point P26 (81.28, 58.928)
  point P32 (220.98, -526.034)
  point P33 (220.98, 58.928)
  point P35 (161.925, -526.034)
  point P36 (161.925, 58.928)
  point P37 (228.6, 0)
  point P38 (161.925, -538.48)
  point P39 (161.925, 71.12)
  point P15 (220.98, 71.12)
  point P41 (-220.98, -538.48)
  point P42 (-220.98, 71.12)
  point P34 (-220.98, 58.928)
  point P20 (-220.98, 0)
  point P31 (-220.98, -526.034)
  point P17 (-220.98, -467.36)
  point P14 (220.98, -538.48)
  point P45 (-161.925, -467.36)
  point P46 (-161.925, 0)
  point P49 (-81.28, -538.48)
  point P50 (-81.28, -526.034)
  point P43 (-161.925, -526.034)
  point P47 (-161.925, 58.928)
  point P44 (-161.925, -538.48)
  point P48 (-161.925, 71.12)
  point P51 (-81.28, 58.928)
  point P52 (-81.28, 71.12)
  point P53 (161.925, -496.697)
  point P55 (81.28, -532.257)
  point P54 (195.58, -532.257)
  point P56 (-161.925, -496.697)
  point P60 (161.925, 29.337)
  point P58 (-161.925, 29.337)
  point P57 (-220.98, -496.697)
  point P59 (-220.98, 29.337)
  point P68 (0, -506.73)
  point P100 (106.68, -532.257)
  point P107 (220.98, -496.697)
  point P108 (191.4525, -496.697)
  point P109 (191.4525, -496.697)
  point P61 (220.98, 29.337)
  point P110 (191.4525, -467.36)
  point P111 (191.4525, -482.0285)
  point P99 (207.9625, -482.0285)
  point P21 (228.6, 71.12)
  point P28 (228.6, 71.12)
  point P66 (-19.05, -506.73)
  point P67 (19.05, -506.73)
  point P18 (228.6, -467.36)
  coincident P5 P6
  perpendicular L2 L3
  coincident P2 P8
  perpendicular L1 L4
  midpoint L3 P9
  midpoint L1 P10
  midpoint L2 P11
  midpoint L4 P12
  coincident L5 P13
  coincident L7 P16
  coincident L7 P19
  coincident L8 P22
  coincident L9 P23
  perpendicular L9 L10
  coincident L1 P27
  perpendicular L1 L11
  coincident L3 P29
  vertical L12
  coincident P30 L13
  perpendicular L4 L14
  coincident P26 L14
  coincident L7 P32
  coincident L7 P33
  coincident L13 P35
  perpendicular L13 L15
  coincident L14 P36
  perpendicular L14 L16
  horizontal P19 P37
  coincident L3 P38
  perpendicular L3 L17
  coincident L1 P39
  perpendicular L1 L18
  vertical L7
  coincident L1 P15
  coincident L3 P41
  coincident L1 P42
  perpendicular L1 L19
  coincident P34 L19
  coincident P20 L19
  coincident P31 L19
  coincident P17 L19
  horizontal L9
  vertical L15
  horizontal L8
  coincident L3 P14
  symmetric L5 P22 P45
  symmetric L5 P23 P46
  symmetric L5 P29 P49
  symmetric L5 P30 P50
  symmetric L5 P35 P43
  symmetric L5 P36 P47
  symmetric L5 P38 P44
  symmetric L5 P39 P48
  symmetric L5 P26 P51
  symmetric L5 P27 P52
  vertical P26 P30
  midpoint L15 P53
  perpendicular L2 L27
  midpoint L12 P55
  horizontal P54 P55
  symmetric L5 P53 P56
  symmetric L6 P53 P60
  symmetric L6 P56 P58
  symmetric L6 P57 P59
  tangent L31 A1
  tangent A1 L32
  parallel L31 L32
  tangent L32 A2
  tangent L31 A2
  horizontal L33
  coincident L33 P68
  midpoint L33 P68
  coincident L5 P68
  horizontal P54 P100
  symmetric L5 C1 C4
  symmetric L5 C3 C5
  symmetric L6 C1 C6
  symmetric L6 C3 C7
  symmetric L6 C4 C9
  symmetric L6 C5 C8
  coincident L7 P107
  midpoint L27 P108
  coincident P108 P109
  horizontal L29
  coincident L19 P59
  coincident L7 P61
  horizontal L30
  coincident L8 P110
  midpoint L44 P111
  horizontal P99 P111
  symmetric C2 L44 C10
  symmetric L5 C2 C12
  symmetric L5 C10 C11
  symmetric L6 C2 C13
  symmetric L6 C10 C14
  symmetric L6 C11 C15
  symmetric L6 C12 C16
  vertical L44
  dimension "d2571" distance P6 P29 = 147.32 (= "brace_length + ( material_thickness - dado_material_depth )")
  dimension "d2596" distance P6 P32 = 12.446 (= "dado_material_thickness")
  dimension "d2597" distance P21 P33 = 12.192 (= "material_thickness")
  dimension "d2947" distance P15 P28 = 7.62 (= "material_thickness - dado_material_depth")
  dimension "d2948" distance P8 P42 = 7.62 (= "material_thickness - dado_material_depth")
  dimension "d2951" diameter C1 = 3.2004 (= "hole_screw")
  dimension "d2959" diameter A1 = 3.2004 (= "hole_screw")
  dimension "d2960" distance P9 P68 = 31.75
  dimension "d2961" distance P66 P67 = 38.1 (= "slot_screw_width")
  dimension "d2962" = 5.08 (= "dado_screwhead_carpentry / 2")
  dimension "d2972" diameter C2 = 3.2004 (= "hole_screw")
  dimension "d2977" distance P14 P54 = 25.4 (= "hole_screw_brace_offset")
  dimension "d2978" diameter C3 = 3.2004 (= "hole_screw")
  dimension "d2979" distance P29 P100 = 25.4 (= "hole_screw_brace_offset")
  dimension "d2981" distance P99 P111 = 16.51
  dimension "d3020" distance P18 P22 = 66.675 (= "global_cutout_padding * 1.5")
  dimension "d3022" distance P6 P16 = 71.12 (= "global_shelf_height")
  dimension "d2965" R-Pattern1-uDistance = 165.1
  dimension "d2966" R-Pattern1-vDistance = 0
sketch "printer_top" plane through (0, 0, 538.48) normal (0, 0, 1) x axis (1, 0, 0)
  line L1 (88.9, 18.542) -> (228.6, 18.542)
  line L2 (88.9, 30.734) -> (88.9, 18.542)
  line L3 (228.6, 30.734) -> (88.9, 30.734)
  line L4 (0, 0) -> (0, 508)
  line L5 (-88.9, 18.542) -> (-228.6, 18.542)
  line L6 (-88.9, 30.734) -> (-88.9, 18.542)
  line L7 (-228.6, 30.734) -> (-88.9, 30.734)
  line L8 (34.417, 296.799) -> (-34.417, 296.799)
  line L9 (34.417, 211.201) -> (34.417, 296.799)
  line L10 (-34.417, 211.201) -> (34.417, 211.201)
  line L11 (-34.417, 296.799) -> (-34.417, 211.201)
  line L12 (0, 211.201) -> (0, 296.799)
  line L13 (34.417, 254) -> (-34.417, 254)
  line L14 (-47.117, 198.501) -> (47.117, 198.501)
  line L15 (-47.117, 309.499) -> (-47.117, 198.501)
  line L16 (47.117, 309.499) -> (-47.117, 309.499)
  line L17 (47.117, 198.501) -> (47.117, 309.499)
  line L18 (-47.117, 458.216) -> (-47.117, 309.499)
  line L19 (47.117, 134.62) -> (47.117, 198.501)
  line L20 (-42.037, 129.54) -> (42.037, 129.54)
  line L21 (-47.117, 198.501) -> (-47.117, 134.62)
  line L22 (-12.7, 254) -> (-12.7, 309.499)
  line L23 (-12.7, 445.516) -> (-12.7, 309.499)
  line L24 (47.117, 495.808) -> (-47.117, 495.808)
  line L25 (-25.4, 458.216) -> (-47.117, 458.216)
  line L26 (25.4, 458.216) -> (47.117, 458.216)
  line L27 (12.7, 445.516) -> (12.7, 309.499)
  line L28 (12.7, 254) -> (12.7, 309.499)
  line L29 (47.117, 483.616) -> (-47.117, 483.616)
  line L30 (220.98, 139.7) -> (-220.98, 139.7)
  line L31 (47.117, 458.216) -> (47.117, 309.499)
  line L32 (228.6, 18.542) -> (228.6, 30.734)
  line L33 (-228.6, 18.542) -> (-228.6, 30.734)
  line L34 (47.117, 458.216) -> (47.117, 495.808)
  line L35 (-47.117, 458.216) -> (-47.117, 495.808)
  circle C1 centre (127, 24.638) radius 1.6002
  circle C2 centre (211.6667, 24.638) radius 1.6002
  circle C3 centre (-127, 24.638) radius 1.6002
  circle C4 centre (-211.6667, 24.638) radius 1.6002
  circle C5 centre (34.417, 296.799) radius 1.6002
  circle C6 centre (-34.417, 296.799) radius 1.6002
  circle C7 centre (-34.417, 211.201) radius 1.6002
  circle C8 centre (34.417, 211.201) radius 1.6002
  arc A1 centre (0, 254) radius 12.7 clockwise from (0, 241.3) to (-12.7, 254)
  arc A2 centre (-25.4, 445.516) radius 12.7 clockwise from (-25.4, 458.216) to (-12.7, 445.516)
  arc A3 centre (25.4, 445.516) radius 12.7 clockwise from (12.7, 445.516) to (25.4, 458.216)
  arc A4 centre (0, 254) radius 12.7 clockwise from (12.7, 254) to (0, 241.3)
  arc A5 centre (42.037, 134.62) radius 5.08 clockwise from (47.117, 134.62) to (42.037, 129.54)
  arc A6 centre (-42.037, 134.62) radius 5.08 clockwise from (-42.037, 129.54) to (-47.117, 134.62)
  arc A7 centre (0, 296.799) radius 12.7 clockwise from (-12.7, 296.799) to (12.7, 296.799)
  circle C9 centre (21.717, 489.712) radius 1.6002
  circle C10 centre (-21.717, 489.712) radius 1.6002
  point P2 (0, 0)
  point P3 (0, 0)
  point P4 (228.6, 18.542)
  point P10 (-228.6, 18.542)
  point P5 (88.9, 18.542)
  point P11 (-88.9, 18.542)
  point P6 (88.9, 30.734)
  point P12 (-88.9, 30.734)
  point P7 (228.6, 30.734)
  point P13 (-228.6, 30.734)
  point P35 (228.6, 18.542)
  point P23 (0, 296.799)
  point P24 (0, 211.201)
  point P25 (-34.417, 254)
  point P26 (34.417, 254)
  point P27 (0, 254)
  point P18 (34.417, 296.799)
  point P20 (34.417, 296.799)
  point P19 (-34.417, 296.799)
  point P28 (-34.417, 296.799)
  point P22 (-34.417, 211.201)
  point P29 (-34.417, 211.201)
  point P21 (34.417, 211.201)
  point P30 (34.417, 211.201)
  point P36 (228.6, 30.734)
  point P37 (-12.7, 309.499)
  point P38 (-12.7, 254)
  point P40 (0, 241.3)
  point P39 (0, 254)
  point P49 (12.7, 309.499)
  point P50 (12.7, 254)
  point P52 (0, 241.3)
  point P41 (-12.7, 445.516)
  point P48 (12.7, 445.516)
  point P42 (-47.117, 458.216)
  point P45 (47.117, 458.216)
  point P43 (-25.4, 458.216)
  point P46 (25.4, 458.216)
  point P63 (88.9, 24.638)
  point P14 (127, 24.638)
  point P15 (211.6667, 24.638)
  point P65 (-228.6, 18.542)
  point P64 (-228.6, 30.734)
  point P51 (0, 254)
  point P66 (0, 483.616)
  point P68 (-47.117, 458.216)
  point P62 (47.117, 495.808)
  point P67 (-47.117, 495.808)
  point P70 (12.7, 296.799)
  point P69 (-12.7, 296.799)
  point P71 (0, 296.799)
  point P74 (47.117, 483.616)
  point P75 (-47.117, 483.616)
  point P72 (21.717, 489.712)
  point P8 (0, 508)
  coincident P2 P3
  perpendicular L1 L2
  horizontal L3
  symmetric P4 L4 P10
  symmetric P5 L4 P11
  symmetric P6 L4 P12
  symmetric P7 L4 P13
  symmetric L4 C1 C3
  symmetric L4 C2 C4
  coincident P4 P35
  horizontal L8
  vertical L9
  horizontal L10
  vertical L11
  midpoint L8 P23
  midpoint L10 P24
  midpoint L11 P25
  midpoint L9 P26
  midpoint L12 P27
  midpoint L4 P27
  coincident P18 P20
  coincident P19 P28
  coincident P22 P29
  coincident P21 P30
  coincident P7 P36
  perpendicular L14 L19
  perpendicular L15 L20
  perpendicular L14 L21
  coincident L16 P37
  coincident L13 P38
  vertical L22
  coincident L4 P40
  coincident P27 P39
  perpendicular L16 L23
  perpendicular L18 L25
  tangent L25 A2
  tangent L23 A2
  symmetric L12 P37 P49
  symmetric L12 P38 P50
  symmetric L12 P40 P52
  symmetric L12 A1 A4
  symmetric L12 P41 P48
  symmetric L12 P42 P45
  symmetric L12 P43 P46
  symmetric L12 A2 A3
  tangent L19 A5
  tangent L20 A5
  tangent L21 A6
  equal A5 A6
  tangent L20 A6
  horizontal L24
  vertical L31
  horizontal L29
  midpoint L2 P63
  horizontal P14 P63
  horizontal P15 P63
  symmetric P4 L4 P65
  symmetric P7 L4 P64
  vertical P51 P66
  symmetric L12 P45 P68
  symmetric L12 P62 P67
  coincident L28 P70
  coincident L22 P69
  tangent L22 A7
  tangent L28 A7
  coincident P23 P71
  symmetric L12 C9 C10
  vertical L34
  coincident L34 P74
  coincident L29 P66
  coincident L35 P75
  dimension "d624" distance P5 P6 = 12.192 (= "material_thickness")
  dimension "d635" diameter C1 = 3.2004 (= "hole_screw")
  dimension "d638" diameter C2 = 3.2004 (= "hole_screw")
  dimension "d1414" diameter C5 = 3.2004 (= "hole_screw")
  dimension "d1415" distance P19 P20 = 68.834
  dimension "d1416" distance P19 P22 = 85.598
  dimension "d1417" diameter C6 = 3.2004 (= "hole_screw")
  dimension "d1418" diameter C7 = 3.2004 (= "hole_screw")
  dimension "d1419" diameter C8 = 3.2004 (= "hole_screw")
  dimension "d2544" distance P4 P5 = 139.7 (= "brace_length")
  dimension "d2609" = -12.7
  dimension "d2985" distance P27 P38 = 12.7
  dimension "d2988" radius A2 = 12.7
  dimension "d2992" radius A5 = 5.08
  dimension "d2993" distance L20 L30 = 10.16
  dimension "d2997" distance L25 L29 = 25.4
  dimension "d2998" distance P14 P63 = 38.1 (= "hole_screw_brace_offset * 1.5")
  dimension "d2999" distance P15 L32 = 16.9333 (= "hole_screw_brace_offset / 1.5")
  dimension "d3003" diameter C9 = 3.2004 (= "hole_screw")
  dimension "d3562" distance P62 P72 = 25.4 (= "hole_screw_brace_offset")
  dimension "d3563" distance P8 P62 = 12.192 (= "material_thickness")
  dimension "d3564" distance P62 P74 = 12.192 (= "material_thickness")
  dimension "d3565" distance P66 P72 = 6.096 (= "material_thickness / 2")
work_plane "WorkPlane12" RotateAngle 90
sketch "printer_bracket_top_left" plane through (0, 30.734, 0) normal (0, -1, 0) x axis (-1, 0, 0)
  line L1 (-220.98, -530.86) -> (-88.9, -530.86)
  line L2 (-220.98, -488.188) -> (-220.98, -530.86)
  line L3 (-176.53, -488.188) -> (-220.98, -488.188)
  line L4 (-88.9, -521.97) -> (-176.53, -488.188)
  line L5 (-88.9, -530.86) -> (-88.9, -521.97)
  circle C1 centre (-195.58, -508) radius 9.7155
  circle C2 centre (-195.58, -508) radius 12.7
  point P9 (-88.9, -530.86)
  point P10 (-88.9, -538.48)
  point P3 (-220.98, -488.188)
  point P6 (-228.6, -488.188)
  point P4 (-176.53, -488.188)
  point P5 (-88.9, -521.97)
  point P8 (-195.58, -508)
  horizontal L1
  concentric C1 C2
  coincident L5 P9
  vertical P9 P10
  horizontal L3
  vertical L2
  vertical L5
  horizontal P3 P6
  dimension "d2820" diameter C1 = 19.431 (= "hole_switch_button")
  dimension "d2821" diameter C2 = 25.4 (= "switch_diameter")
  dimension "d2822" distance P3 P4 = 44.45 (= "global_cutout_padding")
  dimension "d2823" distance P5 P9 = 8.89
  dimension "d2824" distance L1 P8 = 22.86
  dimension "d2825" distance L2 P8 = 25.4
  dimension "d2827" distance P3 P6 = 7.62 (= "material_thickness - dado_material_depth")
  dimension "d3382" distance P9 P10 = 7.62 (= "material_thickness - dado_material_depth")
extrude "Extrude50" new body sketch "printer_bracket_top_left" along normal blind 12.192 (= "material_thickness") bodies "printer_brace_right"
extrude "Extrude51" sketch "printer_bracket_top_left" profile of C1 C2 no distance stored
extrude "Extrude1" new body sketch "printer_bottom" profile of L3 C1 C2 C3 C4 C5 C6 C7 C8 L9 L10 L12 L20 L21 L22 L23 L24 L25 L26 L27 L28 L29 L30 L31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 along normal blind 12.192 (= "material_thickness") bodies "printer_bottom_bracket_right", "printer_bottom_front", "printer_bottom_bracket_left"
extrude "Extrude5" sketch "printer_bottom" profile of C1 C2 C3 C4 C5 C6 C7 C8 no distance stored
extrude "Extrude39" new body sketch "printer_side_right" profile of L1 L2 L3 L36 C1 C2 C3 C4 C5 C6 C7 C8 L43 L45 L9 L10 L11 L12 L13 L14 L15 L16 C9 C10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 no distance stored bodies "printer_side_right"
extrude "Extrude66" sketch "printer_side_right" profile of C1 C2 C3 C4 C5 C6 C7 C8 blind 3.048 (= "dado_bolthead_depth")
extrude "Extrude54" sketch "printer_side_right" profile of L1 L2 L3 L43 L45 L9 L10 L11 L12 L13 L14 L15 L16 C9 C10 L37 L38 L39 L40 C11 C12 C13 C14 L46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 blind 4.572 (= "dado_material_depth")
work_plane "WorkPlane13"
mirror "Mirror2" mirrorStitchTolerance 0.1016 bodies "printer_top_front", "printer_top_bracket_left", "printer_top_bracket_right"
extrude "Extrude48" sketch "printer_top" profile of L1 L2 L3 L5 L6 L7 C1 C2 C3 C4 blind 4.572 (= "dado_material_depth")
extrude "Extrude49" cut sketch "printer_top" profile of C1 C2 C3 C4 to an object
mirror "Mirror3" mirrorStitchTolerance 0.1016 bodies "printer_side_left", "printer_brace_left"
extrude "Extrude52" new body sketch "printer_back" profile of L7 L8 L13 L15 L19 L21 L27 L28 L31 A1 L32 A2 A4 L34 A3 L35 L36 A5 L37 A6 L38 A7 A8 L39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 no distance stored bodies "printer_back_support_top_a"
extrude "Extrude55" new body sketch "printer_back" profile of L3 L7 L8 L12 L13 L15 L17 L19 L20 L21 L25 L27 C1 L28 L31 A1 L32 A2 A4 L34 A3 L35 L36 A5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 no distance stored bodies "printer_back_support_top_b"
extrude "Extrude56" cut sketch "printer_back" profile of L1 L3 L7 L11 L12 L13 L14 L17 L18 L19 L20 L24 L25 L26 C1 C3 C4 C5 C6 C7 C8 C9 along normal blind 4.572 (= "dado_material_depth")
extrude "Extrude57" new body sketch "printer_back" profile of L7 L8 L9 L10 L15 L16 L19 L21 L22 L23 L27 L28 L29 L30 C2 C10 C11 C12 C13 C14 C15 C16 no distance stored bodies "printer_back_left", "printer_back_right"
draft "Draft1" Angle1 45 Angle2 0
extrude "Extrude59" sketch "printer_back" profile of L15 L21 L31 A1 L32 A2 A4 L34 A3 L35 L36 A5 L37 A6 L38 A7 A8 L39 L40 A9 L41 A10 L42 A11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 blind 4.572 (= "dado_material_depth")
mirror "Mirror7" mirrorStitchTolerance 0.1016 bodies "printer_back_support_bottom_a", "printer_back_support_bottom_b"
extrude "Extrude60" new body sketch "printer_top" profile of C5 C6 C7 C8 L14 L15 L16 L17 L31 L18 L19 L20 L21 L22 A1 L23 L24 L25 A2 L26 A3 L27 L28 A4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 no distance stored bodies "printer_top_light_bracket_optional"
extrude "Extrude61" cut sketch "printer_top" profile of L16 L19 L20 L21 L22 L23 L25 A2 L26 A3 L27 L28 L29 L30 A5 A6 L34 L35 A7 against normal blind 6.477 (magnitude of "-material_thickness / 2 - 0.015 in")
extrude "Extrude62" sketch "printer_top" profile of L19 L20 L21 L30 A5 A6 blind 6.477 (= "material_thickness / 2 + 0.015 in")
work_plane "WorkPlane3" sketch "printer_bottom" AlongDistance 71.12 (= "global_shelf_height")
